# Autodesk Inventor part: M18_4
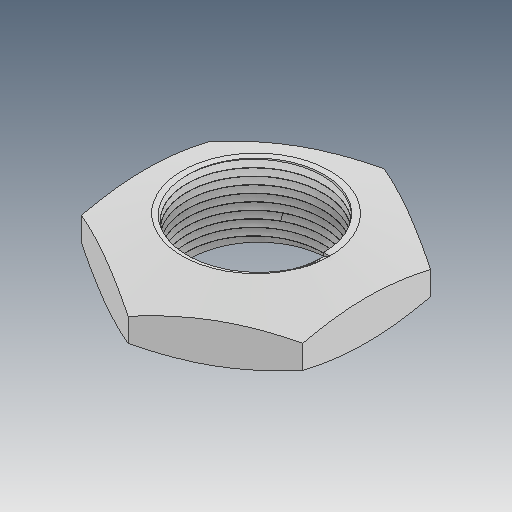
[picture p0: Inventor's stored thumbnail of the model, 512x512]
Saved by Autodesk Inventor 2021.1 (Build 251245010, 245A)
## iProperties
Created: 2019-04
Part Number: M18_4
Material: Ogólny
Document SubType Name: Modeling
Designer: user
Density: 1 g/cm^3
Appearance: Domyślna
Author: user
Revision Number: ÈÎºÎ
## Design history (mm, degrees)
feature "ÊäÈë1"
node "Bryła1"
